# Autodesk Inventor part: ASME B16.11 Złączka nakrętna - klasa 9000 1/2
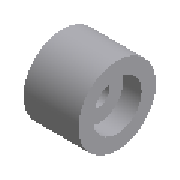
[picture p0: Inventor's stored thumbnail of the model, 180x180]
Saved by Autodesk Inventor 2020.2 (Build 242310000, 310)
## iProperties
Manager: www.cadconsulting.pl
Company: Fabian Stasiak CAD Consulting
NAME: PIPING: ASME B16.11 Coupling - Class 9000
DATA: <meta><inlinegroups number="1" deflen="3.81"></inlinegroups><connections number="2"></connections><angles><a>3.14159265358979</a></angles></meta>
IsCustomPart: 0
Created: 2014-02
Part Number: ASME B16.11 Złączka nakrętna - klasa 9000 1/2
Material: Stal
Description: Złączka nakrętna, kuta, do przyspawania - klasa 9000
Document SubType Name: Modeling
Standard: ASME B16.11
Designer: F.Stasiak
Standard Revision: 2005
Standards Organization: ANSI
Language: pl-PL
Size Designation: 1/2
Categories: <MemberInstance><Categories><Category DisplayName="Rury cienko- i grubościenne" InternalName="4347fa0f-2144-441d-94cd-e3e15c92b736" Mnemonic="TUBEANDPIPE"><Cate
Density: 1 g/cm^3
Appearance: Płyta
Catalog Web Link: www.expertbooks.pl
Author: F.Stasiak
Subject: Zbiór ćwiczeń. Autodesk Inventor 2020. Kurs Professional
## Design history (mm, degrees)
sketch "Sketch1"
  geometry: L1 (0, 0)-(28.956, 0); L2 (0, 0)-(0, 10.858); L3 (0, 10.858)-(9.652, 10.858); L4 (9.652, 10.858)-(9.652, 2.819); L5 (9.652, 2.819)-(19.304, 2.819); L6 (19.304, 2.819)-(19.304, 10.858); L7 (19.304, 10.858)-(28.956, 10.858); L8 (28.956, 10.858)-(28.956, 19.037); L9 (28.956, 19.037)-(0, 19.037); L10 (0, 19.037)-(0, 10.858); L11 (28.956, 10.858)-(28.956, 0)
  constraints: 22 end point, 6 perpendicular, 3 parallel, 1 collinear, 1 horizontal, 1 point on line
  dimensions: "d0" = 5.6388 diameter of L5 L1 (= D); "d1" = 21.717 diameter of L3 L1 (= B); "d2" = 8.1788 distance between parallel lines of L3 L9 (= C1); "d3" = 9.652 distance between parallel lines of L10 L4 (= J1); "d4" = 9.652 distance between parallel lines of L4 L6 (= E1); "d5" = 9.652 distance between parallel lines of L6 L8 (= J1)
revolve "Revolve1" sketch "Sketch1" stored, may be unused: angle "d6" = 90 deg
workaxis "Work Axis1"
workpoint "Work Point1"
workpoint "Work Point2"
workaxis "Work Axis2"
workpoint "Work Point3"
workpoint "Work Point4"
body "Solid1"
other parameters: "B" = 21.717 [user parameter; used in 1 equation term], "D" = 5.6388 [user parameter; used in 1 equation term], "C1" = 8.1788 [user parameter; used in 1 equation term], "J1" = 9.652 [user parameter; used in 2 equation terms], "E1" = 9.652 [user parameter; used in 1 equation term], "Size_Designation" = 5 [user parameter]
